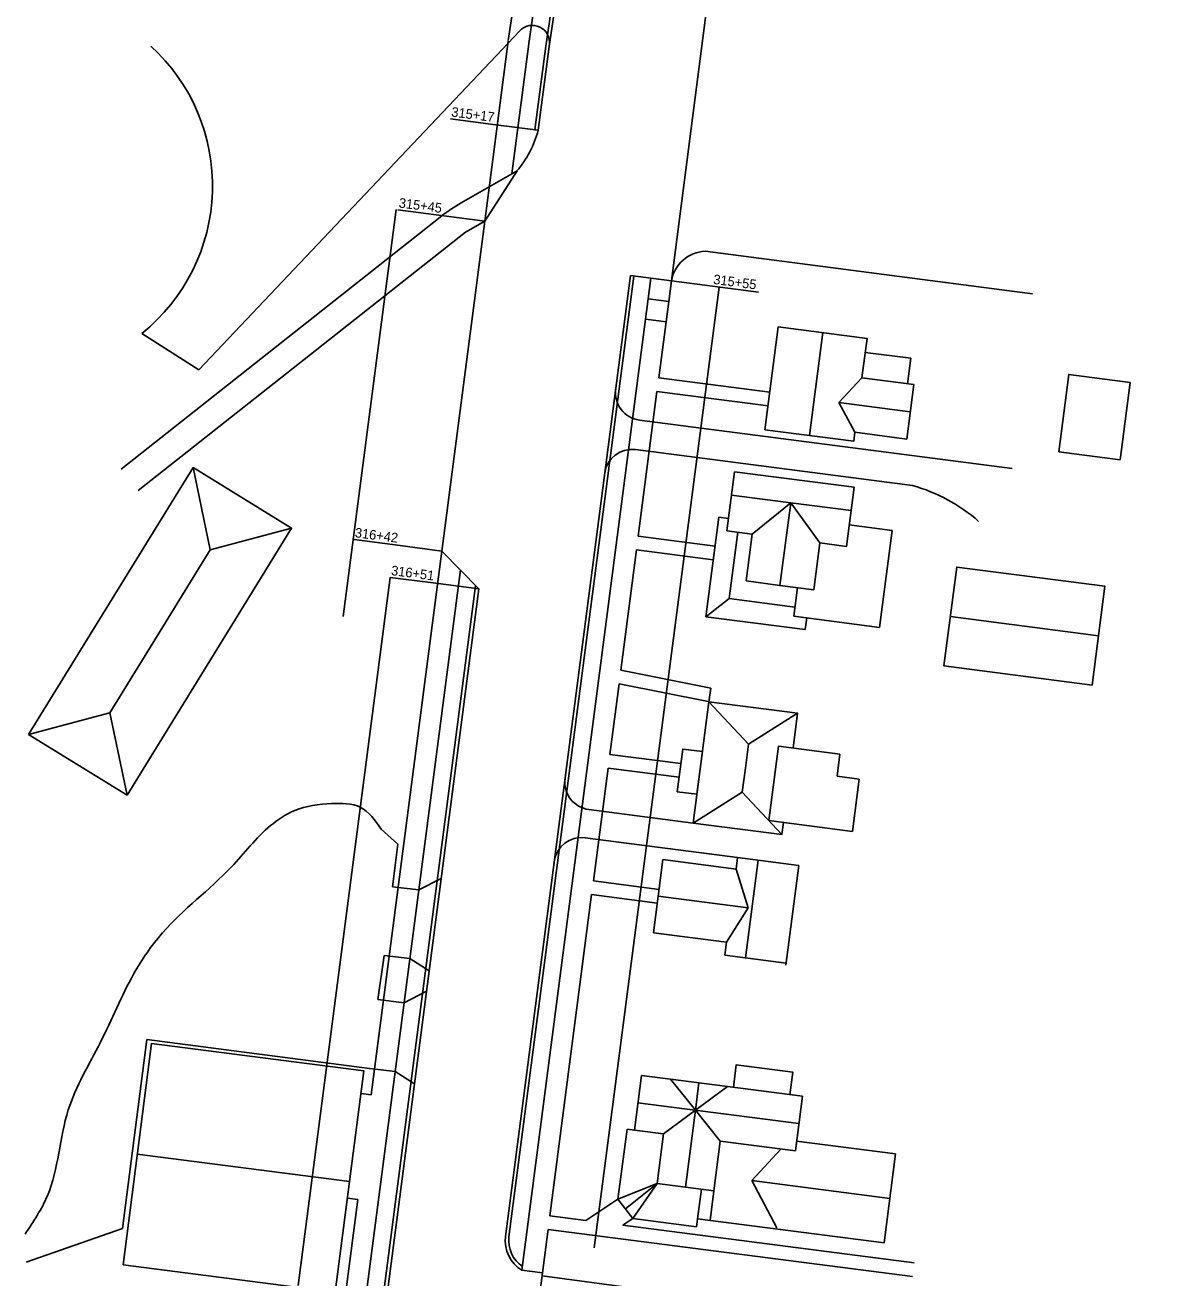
# Model space of a CAD drawing. Extents: x 107766 to 4387554, y 20109 to 1193017.
# Drawn here: x 1746471.7 to 1746805.4, y 279099 to 279463 of the extents above; entities that cross this region are included whole.
import ezdxf

# ---------------------------------------------------------------- set-up
doc = ezdxf.new("R2010")
doc.units = 0
for name, color, linetype in [('GM_X_US_Route', 7, 'Continuous'), ('GM_X_US_Shield', 7, 'Continuous'), ('Level 60', 7, 'Continuous'), ('SC_Scratch1', 7, 'Continuous'), ('SC_Scratch10', 7, 'Continuous'), ('SC_Scratch5', 7, 'Continuous'), ('SC_Scratch8', 7, 'Continuous')]:
    doc.layers.add(name, color=color, linetype=linetype)

msp = doc.modelspace()

# ---------------------------------------------------------------- linework, layer by layer
at = {"layer": 'GM_X_US_Route'}
for p, q in [((1746652.9, 279383.52), (1746653.68, 279389.47)), ((1746653.68, 279389.47), (1746659.63, 279388.7)), ((1746658.85, 279382.75), (1746659.63, 279388.7)), ((1746652.13, 279377.57), (1746652.9, 279383.52)), ((1746652.9, 279383.52), (1746658.85, 279382.75)), ((1746658.08, 279376.8), (1746658.85, 279382.75)), ((1746652.13, 279377.57), (1746658.08, 279376.8))]:
    msp.add_line(p, q, dxfattribs=at)
msp.add_lwpolyline([(1746658.85, 279382.75), (1746659.63, 279388.7), (1746653.68, 279389.47), (1746652.9, 279383.52), (1746658.85, 279382.75)], dxfattribs=at)
at = {"layer": 'GM_X_US_Shield'}
for p, q in [((1746579.63, 279409.44), (1746564.26, 279291.17)), ((1746673.51, 279386.89), (1746637.22, 279107.69)), ((1746577.84, 279302.55), (1746551.1, 279096.78))]:
    msp.add_line(p, q, dxfattribs=at)
at = {"layer": 'Level 60'}
for p, q in [((1746522.31, 279362.88), (1746615.59, 279461.39)), ((1746614.76, 279420.65), (1746598.57, 279411.39)), ((1746499.71, 279334.03), (1746592.41, 279407.23)), ((1746605.42, 279406.09), (1746599.82, 279402.89)), ((1746504.67, 279327.75), (1746599.82, 279402.89)), ((1746669.45, 279397.3), (1746669.45, 279397.3)), ((1746669.45, 279397.3), (1746764.59, 279384.94)), ((1746758.1, 279385.78), (1746758.1, 279385.78)), ((1746522.31, 279362.88), (1746505.72, 279373.43)), ((1746650.34, 279348.25), (1746758.72, 279334.17)), ((1746649.22, 279339.68), (1746729.75, 279329.21)), ((1746665.98, 279231.14), (1746635.63, 279235.09)), ((1746580.13, 279225.01), (1746575.31, 279229.4)), ((1746678.89, 279221.12), (1746634.56, 279226.88)), ((1746578.53, 279212.66), (1746580.13, 279225.01)), ((1746586.21, 279211.75), (1746578.53, 279212.66)), ((1746592.69, 279215.08), (1746586.21, 279211.75)), ((1746574.26, 279179.84), (1746576.15, 279192.65)), ((1746583.61, 279191.76), (1746576.15, 279192.65)), ((1746589.2, 279188.18), (1746583.61, 279191.76)), ((1746581.94, 279178.93), (1746574.26, 279179.84)), ((1746588.42, 279182.26), (1746581.94, 279178.93)), ((1746507.19, 279168.23), (1746500.05, 279113.3)), ((1746571.88, 279159.82), (1746507.19, 279168.23)), ((1746579.34, 279158.94), (1746571.88, 279159.82)), ((1746584.93, 279155.36), (1746579.34, 279158.94)), ((1746500.05, 279113.3), (1746472.1, 279103.54))]:
    msp.add_line(p, q, dxfattribs=at)
for centre, radius, start, end in [((1746619.22, 279457.96), 5, 351.6112, 136.5624), ((1746471.22, 279416.31), 55.03, 308.8186, 47.6089), ((1746623.39, 279367.99), 50, 119.7681, 128.2956), ((1746669.92, 279386.86), 10.46, 92.5869, 169.8625), ((1746651.37, 279356.19), 8, 172.5947, 262.5947), ((1746648.19, 279331.75), 8, 82.5947, 172.5947), ((1746716.74, 279282.3), 48.69, 48.5812, 74.4989), ((1746636.66, 279243.02), 8, 172.5947, 262.5947), ((1746633.53, 279218.94), 8, 82.5947, 172.5947)]:
    msp.add_arc(centre, radius, start, end, dxfattribs=at)
msp.add_spline([(1746575.31, 279229.4), (1746569.2, 279235.72), (1746560.88, 279236.8), (1746550.16, 279234.78), (1746543.12, 279230.41), (1746531.69, 279218.38), (1746511.69, 279199.23), (1746503.32, 279187.28), (1746493.69, 279167.49), (1746484.32, 279147.79), (1746478.25, 279122.84), (1746471.75, 279111.69)], degree=3, dxfattribs=at)
at = {"layer": 'SC_Scratch1'}
for p, q in [((1746638.26, 279593.91), (1746618.17, 279457.66)), ((1746629.22, 279573.71), (1746612.23, 279458.54)), ((1746653.68, 279389.47), (1746659.63, 279388.7)), ((1746688.26, 279356.41), (1746655.97, 279360.57)), ((1746687.75, 279352.44), (1746655.45, 279356.6)), ((1746687.94, 279353.95), (1746687.94, 279353.95)), ((1746649.98, 279314.51), (1746672.32, 279311.63)), ((1746649.47, 279310.54), (1746671.8, 279307.66)), ((1746671.08, 279270.37), (1746644.92, 279275.57)), ((1746670.3, 279266.45), (1746644.41, 279271.59)), ((1746670.57, 279266.4), (1746671.08, 279270.37)), ((1746662.41, 279248.44), (1746641.74, 279251.1)), ((1746661.9, 279244.47), (1746641.23, 279247.14)), ((1746656.04, 279211.88), (1746636.96, 279214.34)), ((1746655.52, 279207.91), (1746636.45, 279210.37)), ((1746569.37, 279152.52), (1746572.41, 279152.13)), ((1746565.45, 279122.11), (1746568.46, 279121.73)), ((1746644.11, 279121.84), (1746634.8, 279115.67)), ((1746634.8, 279115.67), (1746624.32, 279117.02)), ((1746648.43, 279116.24), (1746645.49, 279114.29)), ((1746730.22, 279103.37), (1746645.49, 279114.29)), ((1746617.75, 279113.08), (1746616.21, 279101.18)), ((1746623.7, 279112.32), (1746622.16, 279100.42)), ((1746729.71, 279099.4), (1746623.8, 279113.06)), ((1746616.21, 279101.18), (1746622.16, 279100.42))]:
    msp.add_line(p, q, dxfattribs=at)
for points in [[(1746612.21, 279458.33), (1746605.42, 279406.09)], [(1746618.16, 279457.56), (1746613.25, 279419.78)], [(1746652.13, 279377.57), (1746617.75, 279113.08)], [(1746658.08, 279376.8), (1746655.97, 279360.57)], [(1746655.45, 279356.6), (1746649.98, 279314.51)], [(1746592.95, 279310.2), (1746572.41, 279152.13)], [(1746649.47, 279310.54), (1746644.92, 279275.57)], [(1746598.29, 279304.7), (1746570.93, 279094.19), (1746542.44, 278867.49), (1746537.4, 278800.71), (1746537.6, 278777.19)], [(1746644.41, 279271.59), (1746641.74, 279251.1)], [(1746641.23, 279247.14), (1746636.96, 279214.34)], [(1746636.45, 279210.37), (1746624.32, 279117.02)], [(1746568.46, 279121.73), (1746564.98, 279094.95), (1746536.47, 278868.09), (1746531.4, 278800.91), (1746531.6, 278777.14)], [(1746623.8, 279113.06), (1746623.7, 279112.32)]]:
    msp.add_lwpolyline(points, dxfattribs=at)
at = {"layer": 'SC_Scratch10'}
for p, q in [((1746649.6, 279629.7), (1746624.11, 279456.79)), ((1746659.63, 279388.7), (1746672.03, 279484.17)), ((1746607.81, 279434.19), (1746595.44, 279435.8)), ((1746614.76, 279420.65), (1746605.42, 279406.09)), ((1746593.52, 279407.64), (1746580.16, 279409.37)), ((1746605.42, 279406.09), (1746592.95, 279310.2)), ((1746659.63, 279388.7), (1746647.73, 279390.24)), ((1746684.92, 279385.41), (1746671.59, 279387.14)), ((1746580.75, 279311.79), (1746567.4, 279313.53)), ((1746603.62, 279299.2), (1746592.95, 279310.2)), ((1746590.34, 279300.93), (1746577.93, 279302.54)), ((1746619.65, 279080.89), (1746622.16, 279100.42))]:
    msp.add_line(p, q, dxfattribs=at)
for points in [[(1746624.11, 279456.79), (1746620.95, 279432.49)], [(1746607.81, 279434.19), (1746620.95, 279432.49)], [(1746593.52, 279407.64), (1746605.42, 279406.09)], [(1746647.73, 279390.24), (1746611.44, 279111.04)], [(1746671.59, 279387.14), (1746659.63, 279388.7)], [(1746580.75, 279311.79), (1746592.95, 279310.2)], [(1746603.62, 279299.2), (1746576.88, 279093.43), (1746548.42, 278866.89), (1746543.41, 278800.51), (1746543.62, 278774.4)], [(1746590.34, 279300.93), (1746603.62, 279299.2)], [(1746622.05, 279099.57), (1746923.73, 279059.04), (1747044.13, 279042.82), (1747081.06, 279040.17), (1747112.67, 279041.25), (1747148.56, 279047.01), (1747306.84, 279085.18), (1747413.8, 279115.82)]]:
    msp.add_lwpolyline(points, dxfattribs=at)
for centre, radius, start, end in [((1746591.11, 279440.55), 30.9, 319.9138, 344.8764), ((1746621.35, 279109.75), 10, 172.5947, 239.0166)]:
    msp.add_arc(centre, radius, start, end, dxfattribs=at)
at = {"layer": 'SC_Scratch5'}
for p, q in [((1746648.61, 279629.84), (1746623.12, 279456.93)), ((1746619.96, 279432.61), (1746620.95, 279432.49))]:
    msp.add_line(p, q, dxfattribs=at)
for points in [[(1746623.11, 279456.92), (1746619.96, 279432.61)], [(1746648.72, 279390.11), (1746612.43, 279110.91)], [(1746602.73, 279300.12), (1746575.89, 279093.55), (1746547.42, 278866.99), (1746542.41, 278800.54), (1746542.62, 278774.4)]]:
    msp.add_lwpolyline(points, dxfattribs=at)
msp.add_arc((1746621.35, 279109.75), 9, 172.5947, 236.2069, dxfattribs=at)
at = {"layer": 'SC_Scratch8'}
for p, q in [((1746703.63, 279373.67), (1746699.74, 279343.79)), ((1746716, 279367.92), (1746729.21, 279366.2)), ((1746729.21, 279366.2), (1746728.25, 279358.79)), ((1746708.33, 279353.34), (1746715.04, 279360.5)), ((1746715.04, 279360.5), (1746730.1, 279358.55)), ((1746728.05, 279342.75), (1746730.1, 279358.55)), ((1746708.33, 279353.34), (1746712.98, 279344.71)), ((1746708.33, 279353.34), (1746729.07, 279350.65)), ((1746712.98, 279344.71), (1746728.05, 279342.75)), ((1746525.61, 279310.55), (1746520.64, 279334.47)), ((1746675.78, 279316.06), (1746678.01, 279333.25)), ((1746678.01, 279333.25), (1746712.77, 279328.73)), ((1746712.77, 279328.73), (1746710.54, 279311.54)), ((1746694.32, 279324.22), (1746677.13, 279326.45)), ((1746694.32, 279324.22), (1746683.14, 279315.1)), ((1746691.2, 279300.22), (1746694.32, 279324.22)), ((1746694.32, 279324.22), (1746702.79, 279312.55)), ((1746694.32, 279324.22), (1746711.89, 279321.93)), ((1746673.41, 279320.02), (1746669.65, 279291.11)), ((1746676.24, 279319.65), (1746673.41, 279320.02)), ((1746723.81, 279316.16), (1746711.35, 279317.78)), ((1746525.61, 279310.55), (1746549.22, 279316.85)), ((1746683.14, 279315.1), (1746675.78, 279316.06)), ((1746678.99, 279315.64), (1746676.48, 279296.37)), ((1746683.14, 279315.1), (1746681.38, 279301.5)), ((1746720.16, 279288.01), (1746723.81, 279316.16)), ((1746511.01, 279286.87), (1746525.61, 279310.55)), ((1746702.79, 279312.55), (1746701.02, 279298.95)), ((1746702.79, 279312.55), (1746710.54, 279311.54)), ((1746691.2, 279300.22), (1746681.38, 279301.5)), ((1746691.2, 279300.22), (1746701.02, 279298.95)), ((1746696.3, 279299.56), (1746695.22, 279291.25)), ((1746676.48, 279296.37), (1746669.65, 279291.11)), ((1746676.48, 279296.37), (1746695.56, 279293.89)), ((1746669.65, 279291.11), (1746698.56, 279287.36)), ((1746695.22, 279291.25), (1746720.16, 279288.01)), ((1746698.56, 279287.36), (1746699, 279290.76)), ((1746783.81, 279285.59), (1746740.74, 279291.19)), ((1746511.01, 279286.87), (1746496.41, 279263.18)), ((1746682.05, 279254.05), (1746670.57, 279266.4)), ((1746496.41, 279263.18), (1746472.8, 279256.89)), ((1746496.41, 279263.18), (1746501.39, 279239.26)), ((1746682.05, 279254.05), (1746696.32, 279263.06)), ((1746681.15, 279247.1), (1746682.05, 279254.05)), ((1746687.95, 279231.86), (1746690.77, 279253.51)), ((1746690.77, 279253.51), (1746708.62, 279251.19)), ((1746708.62, 279251.19), (1746707.78, 279244.75)), ((1746680.25, 279240.15), (1746681.15, 279247.1)), ((1746707.78, 279244.75), (1746714.22, 279243.92)), ((1746714.22, 279243.92), (1746712.24, 279228.7)), ((1746680.25, 279240.15), (1746665.98, 279231.14)), ((1746680.25, 279240.15), (1746691.74, 279227.79)), ((1746687.95, 279231.86), (1746712.24, 279228.7)), ((1746654.4, 279199.25), (1746657.16, 279220.54)), ((1746657.16, 279220.54), (1746678.45, 279217.78)), ((1746678.45, 279217.78), (1746678.89, 279221.12)), ((1746678.89, 279221.12), (1746696.7, 279218.8)), ((1746681.18, 279191.95), (1746684.87, 279220.34)), ((1746681.94, 279206.5), (1746678.45, 279217.78)), ((1746696.7, 279218.8), (1746692.94, 279189.86)), ((1746655.78, 279209.9), (1746681.94, 279206.5)), ((1746681.94, 279206.5), (1746675.69, 279196.49)), ((1746675.69, 279196.49), (1746654.4, 279199.25)), ((1746675.69, 279196.49), (1746675.2, 279192.73)), ((1746675.2, 279192.73), (1746693.01, 279190.41)), ((1746648.89, 279141.91), (1746650.93, 279157.79)), ((1746659.37, 279156.7), (1746650.93, 279157.79)), ((1746666.61, 279147.69), (1746659.37, 279156.7)), ((1746659.37, 279156.7), (1746675.91, 279154.57)), ((1746666.61, 279147.69), (1746667.64, 279155.63)), ((1746666.61, 279147.69), (1746675.91, 279154.57)), ((1746675.91, 279154.57), (1746697.74, 279151.75)), ((1746649.91, 279149.85), (1746696.71, 279143.81)), ((1746697.74, 279151.75), (1746695.69, 279135.88)), ((1746666.61, 279147.69), (1746657.32, 279140.82)), ((1746666.61, 279147.69), (1746663.74, 279125.37)), ((1746666.61, 279147.69), (1746673.86, 279138.69)), ((1746646.74, 279142.19), (1746644.11, 279121.84)), ((1746648.89, 279141.91), (1746646.74, 279142.19)), ((1746657.32, 279140.82), (1746648.89, 279141.91)), ((1746657.32, 279140.82), (1746655.47, 279126.43)), ((1746673.86, 279138.69), (1746672, 279124.3)), ((1746673.86, 279138.69), (1746695.69, 279135.88)), ((1746682.98, 279127.26), (1746691.45, 279136.42)), ((1746724.83, 279134.98), (1746696.05, 279138.69)), ((1746566.07, 279126.98), (1746504.38, 279134.93)), ((1746721.5, 279109.18), (1746724.83, 279134.98)), ((1746655.47, 279126.43), (1746644.11, 279121.84)), ((1746655.47, 279126.43), (1746646.27, 279119.04)), ((1746655.47, 279126.43), (1746648.43, 279116.24)), ((1746672, 279124.3), (1746655.47, 279126.43)), ((1746668.37, 279124.77), (1746667.26, 279116.17)), ((1746682.98, 279127.26), (1746690.29, 279113.54)), ((1746723.17, 279122.08), (1746682.98, 279127.26)), ((1746648.43, 279116.24), (1746644.11, 279121.84)), ((1746672, 279124.3), (1746670.9, 279115.7)), ((1746666.96, 279113.85), (1746648.43, 279116.24)), ((1746667.26, 279116.17), (1746666.96, 279113.85)), ((1746667.26, 279116.17), (1746721.5, 279109.18))]:
    msp.add_line(p, q, dxfattribs=at)
for points in [[(1746712.98, 279344.71), (1746712.65, 279342.11), (1746686.84, 279345.46), (1746690.72, 279375.34), (1746716.53, 279371.99), (1746715.04, 279360.5)], [(1746692.19, 279231.31), (1746691.74, 279227.79), (1746665.98, 279231.14), (1746670.57, 279266.4), (1746696.32, 279263.06), (1746695.01, 279252.96)], [(1746677.67, 279154.34), (1746678.51, 279160.91), (1746694.94, 279158.79), (1746694.1, 279152.22)]]:
    msp.add_lwpolyline(points, dxfattribs=at)
for points in [[(1746772.22, 279339.05), (1746775.13, 279361.5), (1746792.99, 279359.18), (1746790.08, 279336.73)], [(1746472.8, 279256.89), (1746520.64, 279334.47), (1746549.22, 279316.85), (1746501.39, 279239.26)], [(1746738.88, 279276.84), (1746742.61, 279305.55), (1746785.68, 279299.95), (1746781.95, 279271.24)], [(1746667.07, 279239.53), (1746668.68, 279251.9), (1746662.96, 279252.64), (1746661.35, 279240.27)], [(1746500.23, 279102.76), (1746508.53, 279167.1), (1746570.22, 279159.15), (1746561.93, 279094.81)]]:
    msp.add_lwpolyline(points, close=True, dxfattribs=at)

# ---------------------------------------------------------------- texts
at = {"layer": 'SC_Scratch10'}
for s, p in [('315+17', (1746595.54, 279436.49)), ('315+45', (1746580.26, 279410.06)), ('315+55', (1746671.69, 279387.83)), ('316+42', (1746567.5, 279314.22)), ('316+51', (1746578.03, 279303.23))]:
    msp.add_text(s, height=2.8, rotation=352.5947, dxfattribs=at).set_placement(p)

doc.saveas('drawing.dxf')
